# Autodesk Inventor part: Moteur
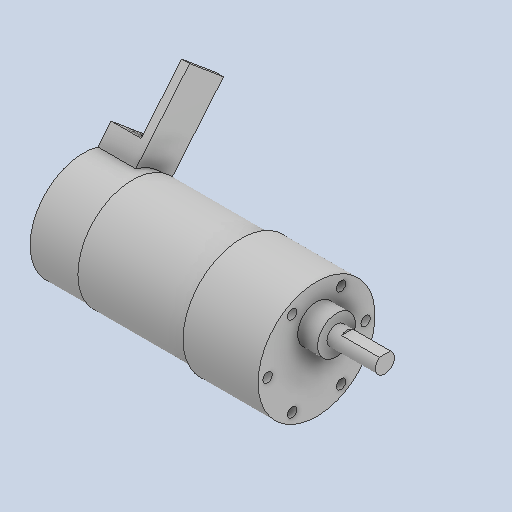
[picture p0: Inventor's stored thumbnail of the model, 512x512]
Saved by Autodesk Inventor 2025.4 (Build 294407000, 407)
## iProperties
Created: 2026-06
Part Number: Moteur
Material: Generic
Document SubType Name: Modeling
Designer: AdminForWorker
Density: 1 g/cm^3
Appearance: Default
Title: Moteur v4
Author: AdminForWorker
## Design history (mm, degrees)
feature "Body1"
body "Solid1"
